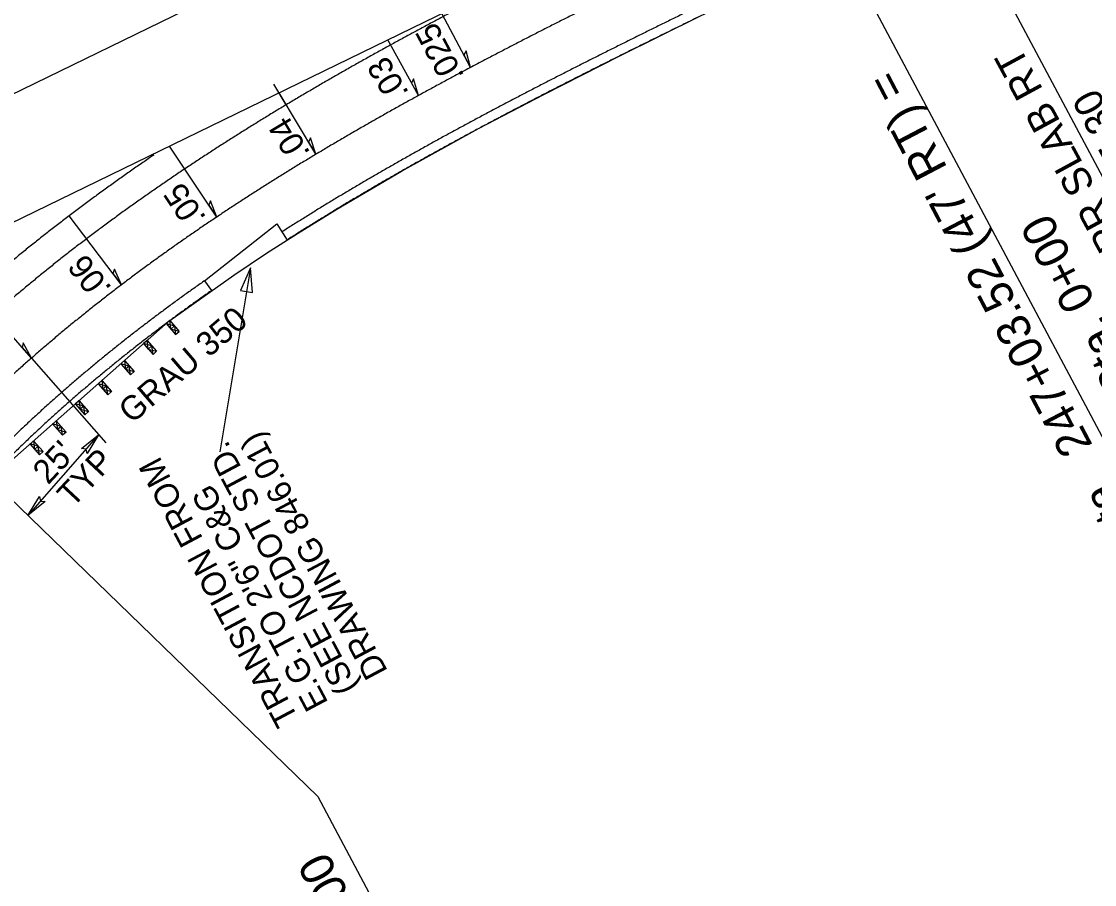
# Model space of a CAD drawing. Extents: x 2389694 to 2405615, y 547005 to 573532.
# Drawn here: x 2402237.1 to 2402460.2, y 570674.4 to 570853.8 of the extents above; entities that cross this region are included whole.
import ezdxf

# ---------------------------------------------------------------- set-up
doc = ezdxf.new("R2010")
doc.units = 0
for name, color, linetype in [('Old_Level_11', 7, 'Continuous'), ('Old_Level_5', 7, 'Continuous'), ('Prop Conc 2ft 6in Curb and Gutter', 7, 'Continuous'), ('Prop Conc Expressway Gutter', 7, 'Continuous'), ('Prop Dimension', 7, 'Continuous'), ('Prop Dimension Text', 7, 'Continuous'), ('Prop EOT', 7, 'Continuous'), ('Prop GRAU 350 Approach CELL', 7, 'Continuous'), ('Prop Guardrail', 7, 'Continuous'), ('Prop Horizontal Alignment', 7, 'Continuous'), ('Prop Horizontal Alignment Curve and Spiral Data', 7, 'Continuous'), ('Prop Horizontal Alignment Tick Small', 7, 'Continuous'), ('Prop Lane Lines', 7, 'Continuous'), ('Prop Super Arrow 1 Lane CELL', 7, 'Continuous'), ('Prop Superelevation Label', 7, 'Continuous')]:
    doc.layers.add(name, color=color, linetype=linetype)

msp = doc.modelspace()

# ---------------------------------------------------------------- linework, layer by layer
at = {"layer": 'Old_Level_5'}
msp.add_line((2402284.69, 570802.6), (2402278.32, 570764.35), dxfattribs=at)
msp.add_lwpolyline([(2402285.1, 570797.46), (2402284.69, 570802.6), (2402282.64, 570797.87)], close=True, dxfattribs=at)
at = {"layer": 'Prop Conc 2ft 6in Curb and Gutter'}
msp.add_arc((2402419.3, 570575.99), 272.5, 151.0902, 272.8811, dxfattribs=at)
msp.add_spline([(2402276.54, 570797.84), (2402276.44, 570797.77), (2402274.36, 570796.3), (2402272.29, 570794.81), (2402270.23, 570793.32), (2402268.19, 570791.81), (2402266.16, 570790.29), (2402264.14, 570788.76), (2402262.13, 570787.22), (2402260.14, 570785.66), (2402258.16, 570784.1), (2402256.2, 570782.51), (2402254.25, 570780.92), (2402252.32, 570779.31), (2402250.4, 570777.69), (2402248.5, 570776.06), (2402246.61, 570774.41), (2402244.74, 570772.75), (2402242.88, 570771.07), (2402241.04, 570769.38), (2402239.22, 570767.68), (2402237.42, 570765.96), (2402235.63, 570764.23), (2402233.86, 570762.49), (2402232.11, 570760.73), (2402230.3, 570758.88)], degree=3, dxfattribs=at)
at = {"layer": 'Prop Conc Expressway Gutter'}
msp.add_spline([(2402390.35, 570863.05), (2402387.92, 570861.87), (2402385.49, 570860.69), (2402383.07, 570859.51), (2402380.65, 570858.33), (2402378.23, 570857.15), (2402375.82, 570855.97), (2402373.4, 570854.79), (2402371, 570853.6), (2402368.59, 570852.42), (2402366.2, 570851.24), (2402363.8, 570850.05), (2402361.41, 570848.86), (2402359.02, 570847.67), (2402356.64, 570846.47), (2402354.26, 570845.28), (2402351.89, 570844.08), (2402349.52, 570842.87), (2402347.16, 570841.67), (2402344.8, 570840.45), (2402342.45, 570839.24), (2402340.1, 570838.02), (2402337.76, 570836.79), (2402335.42, 570835.56), (2402333.1, 570834.32), (2402330.77, 570833.08), (2402328.46, 570831.83), (2402326.15, 570830.58), (2402323.84, 570829.32), (2402321.55, 570828.05), (2402319.26, 570826.77), (2402316.98, 570825.49), (2402314.7, 570824.2), (2402312.44, 570822.9), (2402310.18, 570821.6), (2402307.93, 570820.28), (2402305.69, 570818.96), (2402303.45, 570817.63), (2402301.23, 570816.28), (2402299.01, 570814.93), (2402296.81, 570813.57), (2402294.61, 570812.2), (2402292.42, 570810.83), (2402291.22, 570810.06)], degree=3, dxfattribs=at)
at = {"layer": 'Prop Dimension'}
for p, q in [((2402437.35, 570867.5), (2402484.18, 570779.44)), ((2402239.17, 570783.84), (2402254.62, 570766.21)), ((2402253.13, 570767.92), (2402238.43, 570751.16))]:
    msp.add_line(p, q, dxfattribs=at)
for points in [[(2402249.58, 570765.05), (2402253.13, 570767.92), (2402250.75, 570763.99), (2402250.52, 570764.95)], [(2402241.98, 570754.03), (2402238.43, 570751.16), (2402240.81, 570755.09), (2402241.03, 570754.13)]]:
    msp.add_lwpolyline(points, close=True, dxfattribs=at)
at = {"layer": 'Prop EOT'}
for p, q in [((2401949.14, 570699.46), (2403805.68, 571603.12)), ((2402275.11, 570799.89), (2402290.15, 570811.75)), ((2402290.15, 570811.75), (2402292.3, 570808.37)), ((2402275.11, 570799.89), (2402276.61, 570797.89))]:
    msp.add_line(p, q, dxfattribs=at)
for radius, start, end in [(293, 135.9178, 271.0318), (275, 135.9178, 272.8811), (297, 141.132, 269.5038)]:
    msp.add_arc((2402419.3, 570575.99), radius, start, end, dxfattribs=at)
for points in [[(2402385.97, 570872.05), (2402383.54, 570870.86), (2402381.11, 570869.68), (2402378.69, 570868.5), (2402376.26, 570867.32), (2402373.84, 570866.13), (2402371.42, 570864.95), (2402369, 570863.76), (2402366.58, 570862.58), (2402364.17, 570861.39), (2402361.76, 570860.2), (2402359.35, 570859.01), (2402356.95, 570857.81), (2402354.55, 570856.61), (2402352.15, 570855.41), (2402349.76, 570854.21), (2402347.37, 570853), (2402344.98, 570851.78), (2402342.6, 570850.57), (2402340.22, 570849.34), (2402337.84, 570848.11), (2402335.47, 570846.88), (2402333.11, 570845.64), (2402330.75, 570844.4), (2402328.39, 570843.15), (2402326.04, 570841.89), (2402323.7, 570840.63), (2402321.36, 570839.36), (2402319.02, 570838.08), (2402316.7, 570836.79), (2402314.38, 570835.5), (2402312.06, 570834.2), (2402309.75, 570832.89), (2402307.45, 570831.57), (2402305.15, 570830.24), (2402302.87, 570828.9), (2402300.58, 570827.56), (2402298.31, 570826.2), (2402296.05, 570824.84), (2402293.79, 570823.46), (2402291.54, 570822.07), (2402289.3, 570820.68), (2402287.06, 570819.27), (2402284.84, 570817.85), (2402282.63, 570816.42), (2402280.42, 570814.98), (2402278.23, 570813.53), (2402276.04, 570812.06), (2402273.86, 570810.58), (2402271.7, 570809.09), (2402269.54, 570807.59), (2402267.4, 570806.07), (2402265.27, 570804.55), (2402263.14, 570803), (2402261.03, 570801.45), (2402258.94, 570799.88), (2402256.85, 570798.3), (2402254.78, 570796.7), (2402252.72, 570795.09), (2402250.67, 570793.47), (2402248.64, 570791.83), (2402246.62, 570790.18), (2402244.61, 570788.51), (2402242.62, 570786.83), (2402240.64, 570785.13), (2402238.68, 570783.42), (2402236.73, 570781.69), (2402234.8, 570779.94), (2402232.89, 570778.19), (2402230.99, 570776.41), (2402229.11, 570774.62), (2402227.24, 570772.82), (2402225.4, 570771), (2402223.57, 570769.16), (2402221.72, 570767.27)], [(2402391.22, 570861.26), (2402388.79, 570860.07), (2402386.37, 570858.89), (2402383.94, 570857.71), (2402381.52, 570856.53), (2402379.11, 570855.35), (2402376.7, 570854.17), (2402374.29, 570852.99), (2402371.88, 570851.81), (2402369.48, 570850.63), (2402367.08, 570849.44), (2402364.69, 570848.26), (2402362.3, 570847.07), (2402359.92, 570845.88), (2402357.54, 570844.69), (2402355.16, 570843.49), (2402352.79, 570842.29), (2402350.43, 570841.09), (2402348.07, 570839.89), (2402345.72, 570838.68), (2402343.37, 570837.46), (2402341.03, 570836.24), (2402338.69, 570835.02), (2402336.36, 570833.79), (2402334.04, 570832.56), (2402331.72, 570831.32), (2402329.41, 570830.07), (2402327.1, 570828.82), (2402324.81, 570827.56), (2402322.52, 570826.3), (2402320.24, 570825.03), (2402317.96, 570823.75), (2402315.69, 570822.46), (2402313.43, 570821.17), (2402311.19, 570819.87), (2402308.94, 570818.56), (2402306.71, 570817.24), (2402304.48, 570815.91), (2402302.27, 570814.57), (2402300.06, 570813.23), (2402297.86, 570811.87), (2402295.67, 570810.51), (2402293.49, 570809.14), (2402292.3, 570808.37)], [(2402275.11, 570799.89), (2402275, 570799.81), (2402272.91, 570798.33), (2402270.82, 570796.84), (2402268.75, 570795.34), (2402266.7, 570793.82), (2402264.65, 570792.29), (2402262.62, 570790.75), (2402260.6, 570789.2), (2402258.59, 570787.63), (2402256.6, 570786.05), (2402254.62, 570784.45), (2402252.66, 570782.85), (2402250.71, 570781.23), (2402248.78, 570779.59), (2402246.86, 570777.95), (2402244.96, 570776.28), (2402243.07, 570774.61), (2402241.2, 570772.92), (2402239.34, 570771.22), (2402237.51, 570769.5), (2402235.69, 570767.77), (2402233.88, 570766.02), (2402232.1, 570764.26), (2402230.33, 570762.49), (2402228.51, 570760.63)]]:
    msp.add_spline(points, degree=3, dxfattribs=at)
at = {"layer": 'Prop GRAU 350 Approach CELL'}
for p, q in [((2402267.56, 570791.35), (2402230.06, 570758.26)), ((2402267.94, 570791.67), (2402267.18, 570791.02)), ((2402267.18, 570791.02), (2402269.12, 570788.73)), ((2402267.18, 570791.02), (2402268.91, 570790.53)), ((2402267.94, 570791.67), (2402269.88, 570789.38)), ((2402268.15, 570789.88), (2402267.94, 570791.67)), ((2402268.91, 570790.53), (2402268.15, 570789.88)), ((2402269.88, 570789.38), (2402268.15, 570789.88)), ((2402268.91, 570790.53), (2402269.12, 570788.73)), ((2402269.12, 570788.73), (2402269.88, 570789.38)), ((2402263.21, 570787.51), (2402262.46, 570786.85)), ((2402262.46, 570786.85), (2402264.44, 570784.6)), ((2402262.46, 570786.85), (2402263.45, 570785.72)), ((2402264.2, 570786.38), (2402262.46, 570786.85)), ((2402263.21, 570787.51), (2402265.19, 570785.26)), ((2402263.45, 570785.72), (2402263.21, 570787.51)), ((2402264.2, 570786.38), (2402263.45, 570785.72)), ((2402264.44, 570784.6), (2402264.2, 570786.38)), ((2402263.45, 570785.72), (2402265.19, 570785.26)), ((2402265.19, 570785.26), (2402264.44, 570784.6)), ((2402257.73, 570782.68), (2402259.75, 570780.39)), ((2402259.49, 570782.2), (2402257.73, 570782.68)), ((2402258.48, 570783.34), (2402260.5, 570781.05)), ((2402258.48, 570783.34), (2402258.74, 570781.53)), ((2402259.49, 570782.2), (2402258.74, 570781.53)), ((2402259.75, 570780.39), (2402259.49, 570782.2)), ((2402258.74, 570781.53), (2402260.5, 570781.05)), ((2402260.5, 570781.05), (2402259.75, 570780.39)), ((2402253.01, 570778.51), (2402255.02, 570776.22)), ((2402254.77, 570778.03), (2402253.01, 570778.51)), ((2402253.76, 570779.17), (2402255.77, 570776.89)), ((2402253.76, 570779.17), (2402254.02, 570777.37)), ((2402254.77, 570778.03), (2402254.02, 570777.37)), ((2402254.02, 570777.37), (2402255.77, 570776.89)), ((2402255.02, 570776.22), (2402254.77, 570778.03)), ((2402249.03, 570775), (2402248.28, 570774.34)), ((2402249.03, 570775), (2402251.04, 570772.73)), ((2402249.03, 570775), (2402249.29, 570773.2)), ((2402255.77, 570776.89), (2402255.02, 570776.22)), ((2402248.28, 570774.34), (2402250.29, 570772.07)), ((2402250.04, 570773.86), (2402248.28, 570774.34)), ((2402250.04, 570773.86), (2402249.29, 570773.2)), ((2402249.29, 570773.2), (2402251.04, 570772.73)), ((2402250.29, 570772.07), (2402250.04, 570773.86)), ((2402244.31, 570770.83), (2402246.38, 570768.48)), ((2402244.31, 570770.83), (2402244.59, 570769)), ((2402251.04, 570772.73), (2402250.29, 570772.07)), ((2402243.56, 570770.17), (2402245.63, 570767.82)), ((2402245.34, 570769.66), (2402243.56, 570770.17)), ((2402245.34, 570769.66), (2402244.59, 570769)), ((2402244.59, 570769), (2402246.38, 570768.48)), ((2402245.63, 570767.82), (2402245.34, 570769.66)), ((2402246.38, 570768.48), (2402245.63, 570767.82)), ((2402239.58, 570766.67), (2402241.57, 570764.42)), ((2402239.58, 570766.67), (2402239.82, 570764.88)), ((2402238.83, 570766.01), (2402240.82, 570763.76)), ((2402240.57, 570765.54), (2402238.83, 570766.01)), ((2402240.57, 570765.54), (2402239.82, 570764.88)), ((2402239.82, 570764.88), (2402241.57, 570764.42)), ((2402240.82, 570763.76), (2402240.57, 570765.54)), ((2402241.57, 570764.42), (2402240.82, 570763.76))]:
    msp.add_line(p, q, dxfattribs=at)
at = {"layer": 'Prop Guardrail'}
for p, q in [((2402361.51, 570846.68), (2402378.13, 570854.88)), ((2402345.69, 570838.64), (2402361.51, 570846.68)), ((2402332.12, 570831.53), (2402345.69, 570838.64)), ((2402316.08, 570822.7), (2402332.12, 570831.53)), ((2402302.62, 570814.79), (2402316.08, 570822.7)), ((2402294.47, 570809.76), (2402302.62, 570814.79)), ((2402288.04, 570805.63), (2402294.47, 570809.76)), ((2402281.23, 570801.1), (2402288.04, 570805.63)), ((2402267.94, 570791.68), (2402281.23, 570801.1))]:
    msp.add_line(p, q, dxfattribs=at)
at = {"layer": 'Prop Horizontal Alignment'}
for centre, radius, start, end in [((2399929.8, 569697.99), 2887.13, 22.84477, 37.67936), ((2402419.3, 570575.99), 287, 135.9178, 272.8811)]:
    msp.add_arc(centre, radius, start, end, dxfattribs=at)
msp.add_spline([(2402380.72, 570882.83), (2402378.29, 570881.65), (2402375.86, 570880.47), (2402373.43, 570879.29), (2402371, 570878.1), (2402368.57, 570876.91), (2402366.14, 570875.73), (2402363.71, 570874.54), (2402361.29, 570873.35), (2402358.86, 570872.15), (2402356.44, 570870.96), (2402354.02, 570869.76), (2402351.6, 570868.55), (2402349.18, 570867.34), (2402346.76, 570866.13), (2402344.35, 570864.92), (2402341.94, 570863.7), (2402339.53, 570862.47), (2402337.12, 570861.24), (2402334.72, 570860.01), (2402332.32, 570858.77), (2402329.92, 570857.52), (2402327.53, 570856.27), (2402325.14, 570855.01), (2402322.75, 570853.74), (2402320.37, 570852.46), (2402317.99, 570851.18), (2402315.61, 570849.89), (2402313.24, 570848.59), (2402310.88, 570847.29), (2402308.51, 570845.97), (2402306.16, 570844.65), (2402303.81, 570843.31), (2402301.46, 570841.97), (2402299.12, 570840.62), (2402296.79, 570839.25), (2402294.46, 570837.88), (2402292.14, 570836.49), (2402289.83, 570835.1), (2402287.52, 570833.69), (2402285.22, 570832.27), (2402282.92, 570830.84), (2402280.64, 570829.4), (2402278.36, 570827.95), (2402276.09, 570826.48), (2402273.83, 570825), (2402271.57, 570823.51), (2402269.33, 570822.01), (2402267.09, 570820.49), (2402264.87, 570818.96), (2402262.65, 570817.41), (2402260.44, 570815.85), (2402258.24, 570814.28), (2402256.06, 570812.69), (2402253.88, 570811.08), (2402251.72, 570809.47), (2402249.56, 570807.83), (2402247.42, 570806.18), (2402245.29, 570804.52), (2402243.18, 570802.84), (2402241.07, 570801.14), (2402238.98, 570799.43), (2402236.9, 570797.7), (2402234.84, 570795.96), (2402232.79, 570794.2), (2402230.75, 570792.42), (2402228.73, 570790.63), (2402226.72, 570788.82), (2402224.73, 570786.99), (2402222.76, 570785.14), (2402220.8, 570783.28), (2402218.86, 570781.4), (2402216.93, 570779.5), (2402215.03, 570777.59), (2402213.14, 570775.66)], degree=3, dxfattribs=at)
at = {"layer": 'Prop Horizontal Alignment Curve and Spiral Data'}
for p, q in [((2402486.84, 570720.34), (2402407.02, 570870.48)), ((2402214.21, 570774.61), (2402298.73, 570692.76)), ((2402298.73, 570692.76), (2402357.17, 570582.86))]:
    msp.add_line(p, q, dxfattribs=at)
at = {"layer": 'Prop Horizontal Alignment Tick Small'}
msp.add_line((2402292.14, 570836.49), (2402289.57, 570840.78), dxfattribs=at)
at = {"layer": 'Prop Lane Lines'}
msp.add_line((2402222.06, 570805.61), (2402420.86, 570902.38), dxfattribs=at)
msp.add_spline([(2402264.57, 570826.03), (2402263.71, 570825.44), (2402261.45, 570823.89), (2402259.2, 570822.32), (2402256.96, 570820.74), (2402254.73, 570819.14), (2402252.51, 570817.53), (2402250.31, 570815.9), (2402248.11, 570814.26), (2402245.92, 570812.6), (2402243.75, 570810.93), (2402241.58, 570809.23), (2402239.43, 570807.53), (2402237.29, 570805.8), (2402235.16, 570804.06), (2402233.05, 570802.3), (2402230.95, 570800.53), (2402228.86, 570798.74), (2402226.79, 570796.93), (2402226.44, 570796.62)], degree=3, dxfattribs=at)
at = {"layer": 'Prop Super Arrow 1 Lane CELL'}
for p, q in [((2402330.45, 570844.24), (2402324.5, 570855.47)), ((2402319.61, 570838.4), (2402313.24, 570849.99)), ((2402298.31, 570826.2), (2402290.64, 570838.99)), ((2402277.68, 570813.16), (2402267.83, 570827.89)), ((2402257.89, 570799.09), (2402247.01, 570813.43)), ((2402239.17, 570783.84), (2402227.3, 570797.38))]:
    msp.add_line(p, q, dxfattribs=at)
for points in [[(2402330.45, 570844.24), (2402329.52, 570847.71), (2402329.07, 570846.85)], [(2402319.61, 570838.4), (2402318.62, 570841.85), (2402318.19, 570840.98)], [(2402298.31, 570826.2), (2402297.2, 570829.61), (2402296.79, 570828.73)], [(2402277.68, 570813.16), (2402276.4, 570816.51), (2402276.04, 570815.61)], [(2402257.89, 570799.09), (2402256.41, 570802.36), (2402256.11, 570801.44)], [(2402239.17, 570783.84), (2402237.46, 570787), (2402237.22, 570786.06)]]:
    msp.add_lwpolyline(points, close=True, dxfattribs=at)

# ---------------------------------------------------------------- texts
at = {"layer": 'Old_Level_11'}
for s, p in [("25'", (2402242.62, 570757.37)), ('TYP', (2402247.74, 570752.6))]:
    msp.add_text(s, height=5, rotation=46.9716, dxfattribs=at).set_placement(p)
at = {"layer": 'Old_Level_5'}
for s, p in [('DRAWING 846.01)', (2402313.33, 570718.78)), ('(SEE NCDOT STD.', (2402307.15, 570715.49)), ('TRANSITION FROM', (2402294.79, 570708.92)), ('E.G.TO 2\'6" C&G', (2402300.97, 570712.21))]:
    msp.add_text(s, height=5, rotation=117.9999, dxfattribs=at).set_placement(p)
at = {"layer": 'Prop Dimension Text'}
for s, height, rotation, p in [('BEG APPR SLAB RT', 6, 118.4733, (2402481.05, 570781.6)), ('L Sta. 247+55.30', 6, 118.4733, (2402489.84, 570786.37)), ('GRAU 350', 5, 40.7051, (2402260, 570770.04))]:
    msp.add_text(s, height=height, rotation=rotation, dxfattribs=at).set_placement(p)
at = {"layer": 'Prop Horizontal Alignment Curve and Spiral Data'}
for s, rotation, p in [("-L- POT Sta.  247+03.52 (47' RT) =", 117.6632, (2402486.7, 570714.56)), ('-Y24LPC- TS Sta. 0+00', 117.3879, (2402496.14, 570726.83)), ('-Y24LPC- SC Sta.  2+00.00', 117.9537, (2402354.49, 570579.87))]:
    msp.add_text(s, height=7, rotation=rotation, dxfattribs=at).set_placement(p)
at = {"layer": 'Prop Superelevation Label'}
for s, rotation, p in [('.025', 117.9037, (2402329.25, 570842.5)), ('.03', 120.945, (2402317.76, 570838.97)), ('.04', 120.945, (2402297.23, 570826.47)), ('.05', 123.7524, (2402275.63, 570813.01)), ('.06', 127.1837, (2402256.01, 570798.39))]:
    msp.add_text(s, height=5, rotation=rotation, dxfattribs=at).set_placement(p)

doc.saveas('drawing.dxf')
